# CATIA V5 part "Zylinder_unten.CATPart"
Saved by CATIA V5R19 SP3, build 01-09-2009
Part number: Zylinder_unten
Bounding box of the stored display mesh (mm): x -15 to 15, y -15 to 15, z -15 to 210
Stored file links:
  C:\Users\Timo\Desktop\Hexapod\Zylinder_unten.CATPart
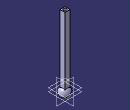
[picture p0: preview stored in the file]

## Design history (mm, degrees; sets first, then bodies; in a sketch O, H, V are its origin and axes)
Set1
  Plane1: type Offset, RefPlane xy-plane, Offset 10
Body1 (main body)
  Sketch1 on xy-plane, origin (0, 0, 0), H (0, 1, 0), V (-1, 0, 0)
    axis line L1 (-130.0335, 0) -> (145.1636, 0)
    point P1 (-130.0335, 0)
    arc A1 centre (0, 0) radius 15 from (15, 0) to (-15, 0) ccw
    point P3 (-15, 0)
    point P4 (15, 0)
    radius A1 = 15
    coincidence: P1 H, P3 L1, P4 L1
    horizontal: L1 H
  Shaft1: profile Sketch1, axis Sketch1.L1, angle 360
  Sketch2 on Plane1, origin (0, 0, 10), H (0, 1, 0), V (-1, 0, 0)
    line L1 (-7.5, 7.5) -> (7.5, 7.5)
    line L2 (7.5, 7.5) -> (7.5, -7.5)
    line L3 (7.5, -7.5) -> (-7.5, -7.5)
    line L4 (-7.5, -7.5) -> (-7.5, 7.5)
    reference intersected line E1 through (0, 0) direction (0, 1) from zx-plane
    reference intersected line E2 through (0, 0) direction (1, 0) from yz-plane
    distance L1 L3 = 15
    distance L2 L4 = 15
    distance E1 L4 = 7.5
    distance L1 E2 = 7.5
    horizontal: L1 H, L3 H
    vertical: L2 V, L4 V
  Pad1: profile Sketch2, direction (0, 0, 1), length 200
  Sketch3 on end face of Pad1, origin (-1.2655, -1.2655, 210), H (1, 0, 0), V (0, 1, 0)
    point P1 (1.2655, 1.2655)
    reference projected line E1 (8.7655, -6.2345) -> (8.7655, 8.7655) from edge [face of Pad1 from Sketch2.L3 | end face of Pad1]
    reference projected line E2 (8.7655, 8.7655) -> (-6.2345, 8.7655) from edge [face of Pad1 from Sketch2.L2 | end face of Pad1]
    distance P1 E1 = 7.5
    distance P1 E2 = 7.5
  Hole1: placed by Sketch3, at (0, 0, 210) direction (0, 0, -1), diameter 10, depth 150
